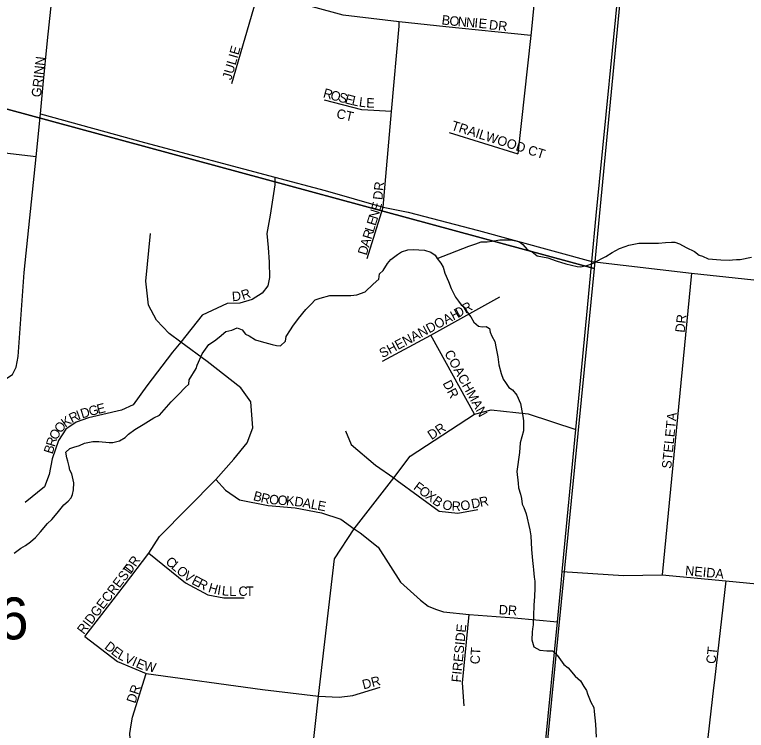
# Model space of a CAD drawing. Extents: x 1310247 to 1552180, y 377264 to 706493.
# Drawn here: x 1437638 to 1441493, y 490370 to 494144 of the extents above; entities that cross this region are included whole.
import ezdxf

# ---------------------------------------------------------------- set-up
doc = ezdxf.new("R2010")
doc.units = 0
for name, color, linetype in [('GM_X_Minor_River', 7, 'Continuous'), ('GM_X_Section', 7, 'Continuous'), ('GM_X_Section_Text', 7, 'Continuous'), ('GM_X_Township_Road', 7, 'Continuous'), ('GM_X_Township_Subdivision', 7, 'Continuous'), ('GM_X_Township_Subdivision_Text', 7, 'Continuous')]:
    doc.layers.add(name, color=color, linetype=linetype)

msp = doc.modelspace()

# ---------------------------------------------------------------- linework, layer by layer
at = {"layer": 'GM_X_Minor_River'}
for points in [[(1439863.8, 492857.5), (1440030.5, 492923), (1440067, 492935.9), (1440095.4, 492945.1), (1440127.5, 492946.1), (1440153.7, 492949.3), (1440194, 492956.1), (1440230.2, 492957), (1440252.2, 492956.3), (1440278.2, 492951.5), (1440298, 492944.9), (1440315.7, 492932.3), (1440339, 492905.5), (1440364.7, 492892.7), (1440390.2, 492871.8), (1440448.1, 492862), (1440491.8, 492844.6), (1440541.5, 492829.1), (1440601.3, 492815.2), (1440619.3, 492814.7), (1440653.6, 492821.6), (1440682, 492830.8), (1440735, 492859.3), (1440753.4, 492868.8), (1440786.1, 492889.8), (1440824.8, 492910.7), (1440855.3, 492921.8), (1440873.5, 492927.3), (1440926, 492937.8), (1440982.2, 492938), (1441030.4, 492938.6), (1441066.6, 492941.5), (1441098.8, 492944.5), (1441116.8, 492944), (1441140.6, 492935.2), (1441176.2, 492916.1), (1441219.7, 492894.7), (1441245.3, 492875.8), (1441263.1, 492869.2), (1441292.8, 492856.3), (1441358.9, 492850.3), (1441403, 492848.9), (1441421.1, 492850.4), (1441441.2, 492851.8), (1441461.3, 492853.2), (1441519.9, 492865.4)], [(1438314.9, 491982), (1438371.5, 492017), (1438401.7, 492032.5), (1438463, 492101.5), (1438501.7, 492140.8), (1438536.4, 492178.3), (1438554.8, 492196), (1438557.2, 492218), (1438594.4, 492277.5), (1438598.7, 492295.5), (1438625.9, 492355.1), (1438660.8, 492404.6), (1438691.2, 492424.1), (1438715.5, 492443.6), (1438750.1, 492473), (1438782.2, 492480.4), (1438810.3, 492491.9), (1438836.1, 492481.3), (1438853.6, 492458.8), (1438873.4, 492450.4), (1438906.9, 492429.6), (1438936.7, 492421), (1438994.2, 492403.7), (1439018.1, 492399.2), (1439038, 492396.8), (1439064.4, 492422.3), (1439068.9, 492446.3), (1439091.6, 492482), (1439104, 492501.8), (1439132.7, 492541.4), (1439171.6, 492588.8), (1439200.1, 492616.3), (1439220.6, 492640), (1439246.7, 492649.5), (1439298.9, 492662.5), (1439352.8, 492663.3), (1439408.7, 492662.2), (1439440.7, 492665.5), (1439485, 492682.7), (1439527.7, 492722), (1439556.2, 492749.5), (1439560.8, 492777.5), (1439579.1, 492795.2), (1439601.8, 492830.9), (1439620.2, 492852.6), (1439654.6, 492878), (1439676.9, 492893.6), (1439709.1, 492902.9), (1439737, 492904.4), (1439767, 492903.7), (1439796.8, 492901.1), (1439830.6, 492890.4), (1439854.2, 492875.8), (1439863.8, 492857.5), (1439883.3, 492833), (1439894.9, 492812.7), (1439904.2, 492780.4), (1439923.2, 492735.8), (1439938.5, 492699.4), (1439961.5, 492654.7), (1439977, 492632.3), (1439990.6, 492613.9), (1440012.2, 492597.4), (1440023.7, 492573.1), (1440041.2, 492550.6), (1440056.6, 492522.2), (1440082.2, 492501.6), (1440102, 492497.1), (1440122, 492498.8), (1440139.8, 492488.3), (1440143.4, 492470.2), (1440152.9, 492447.9), (1440168.3, 492419.5), (1440175.6, 492383.2), (1440184.6, 492338.8), (1440189.8, 492296.5), (1440200.8, 492252.1), (1440212.2, 492221.8), (1440223.8, 492203.4), (1440241.2, 492177), (1440260.9, 492164.5), (1440284.3, 492137.9), (1440303.4, 492093.3), (1440307, 492073.2), (1440316, 492026.8), (1440319.5, 492002.6), (1440318.4, 491948.4), (1440301.2, 491886.5), (1440298.1, 491834.4), (1440284.1, 491734.3), (1440290.9, 491673.9), (1440292.3, 491647.8), (1440303.6, 491615.4), (1440309.2, 491593.2), (1440312.5, 491563), (1440320.2, 491544.8), (1440333.5, 491512.3), (1440351.7, 491427.6), (1440357, 491395.4), (1440361.6, 491323), (1440366.4, 491264.7)], [(1437634.3, 491303.4), (1437670.8, 491330.7), (1437695, 491344.3), (1437721.3, 491363.8), (1437747.8, 491387.4), (1437774.3, 491416.9), (1437811.2, 491460.3), (1437833.5, 491482), (1437862.2, 491515.5), (1437897, 491559), (1437919.4, 491578.6), (1437935.7, 491596.3), (1437942, 491614.3), (1437948.5, 491638.2), (1437949.3, 491674.4), (1437938.3, 491722.8), (1437928.7, 491741.1), (1437925.1, 491761.2), (1437917.7, 491789.5), (1437912.1, 491807.7), (1437906.6, 491835.9), (1437929, 491855.5), (1437949.1, 491863.1), (1437979.2, 491872.5), (1438005.4, 491884.1), (1438031.5, 491889.5), (1438049.5, 491893.2), (1438081.5, 491892.5), (1438135.3, 491887.4), (1438155.2, 491887), (1438189.3, 491896.3), (1438219.6, 491913.7), (1438238, 491931.4), (1438270.4, 491956.9), (1438314.9, 491982)], [(1440366.4, 491264.7), (1440369.7, 491234.5), (1440371.4, 491216.4), (1440374.6, 491178.1), (1440378.1, 491156), (1440379.4, 491119.8), (1440376.5, 491075.7), (1440373.5, 491029.6), (1440372.4, 490973.3), (1440369.5, 490927.2), (1440367, 490905.2), (1440364.7, 490887.2), (1440363.8, 490847), (1440373.1, 490810.7), (1440404.6, 490792), (1440442.5, 490789.1), (1440472.4, 490788.5), (1440495.9, 490766), (1440530.9, 490717), (1440554.5, 490700.5), (1440591.5, 490655.5), (1440619, 490630.9), (1440636.3, 490600.4), (1440651.9, 490580), (1440655.5, 490561.8), (1440674.6, 490519.2), (1440690, 490490.8), (1440691.5, 490468.7), (1440698.1, 490402.3), (1440702.7, 490333.9)]]:
    msp.add_lwpolyline(points, dxfattribs=at)
at = {"layer": 'GM_X_Section'}
for points in [[(1435471.2, 499726.6), (1441204.6, 498140.6), (1440691.2, 492805.3), (1434995.6, 494353)], [(1434995.6, 494353), (1440691.2, 492805.3), (1440171.6, 487550.2), (1434523.9, 489065.4)]]:
    msp.add_lwpolyline(points, close=True, dxfattribs=at)
at = {"layer": 'GM_X_Township_Road'}
for points in [[(1440075.3, 486189.5), (1440078.4, 486259.7), (1440079.3, 486648.8), (1440110.2, 487008.8), (1440147.5, 487410.5), (1440199, 487926), (1440286.6, 488803.3), (1440287.7, 488814.4), (1440345.3, 489393.7), (1440433.9, 490284.4), (1440498.5, 490942), (1440517.4, 491143.5), (1440522, 491207.4), (1440594.8, 491956.1), (1440657.1, 492597.6), (1440679.8, 492841.4), (1440702.4, 493084.3), (1440840.8, 494488.3), (1440884.8, 494943.8), (1440887.9, 494974.8), (1440891, 495006.8)], [(1433702.7, 491387.2), (1433896.9, 491482.8), (1434035.3, 491546.2), (1434171.6, 491591.7), (1434375.3, 491641.9), (1434710.6, 491714.9), (1434801.6, 491758.4), (1435236.4, 491956.4), (1435669.3, 492140.2), (1435775.4, 492168.6), (1435925, 492199.9), (1436237.6, 492256.7), (1436571.1, 492316.4), (1436669.6, 492315.4), (1437183.1, 492261.1), (1437537.7, 492224.9), (1437592, 492222.7), (1437626.3, 492246.3), (1437645.5, 492284.9), (1437655.6, 492340.6), (1437687.7, 492784.8), (1437751.6, 493393.4), (1437774.4, 493620)], [(1437774.4, 493620), (1438322.3, 493469.7), (1439008.5, 493285.9), (1439273.8, 493215.4), (1439579.9, 493129.2), (1439710.8, 493101.7), (1440082, 493005), (1440679.8, 492841.4), (1441204.7, 492780.6), (1441714.2, 492726.8), (1442667.4, 492637.5), (1442992.2, 492599.4), (1443157.4, 492587.5), (1443532.5, 492544.6), (1443863.8, 492520.3), (1444719.2, 492429.1), (1445497, 492347.4)]]:
    msp.add_lwpolyline(points, dxfattribs=at)
at = {"layer": 'GM_X_Township_Subdivision'}
for points in [[(1438781.4, 493779.7), (1438921.8, 494263), (1438949, 494374.8), (1439035.7, 494726.8), (1439094.4, 494924.7), (1439193, 495094.9), (1439277.9, 495285.6), (1439398.8, 495716.4), (1439522.6, 496100.9), (1439593.2, 496358.2), (1439603.6, 496409), (1439659.3, 496679.9), (1439707.8, 497022.1), (1439728.8, 497224.4)], [(1439762, 495211.9), (1440349.5, 495063.9), (1440391.1, 495013.9), (1440420.7, 494951), (1440435.6, 494851.3), (1440404.6, 494525.3), (1440362.7, 494084), (1440357.1, 494032.6), (1440289, 493409.7)], [(1437774.4, 493620), (1437787.7, 493776), (1437810.5, 494007.4), (1437836.2, 494256.7), (1437843.5, 494332.2), (1437871.6, 494523.6), (1437876.3, 494673.5), (1437866.2, 494738.4), (1437832.9, 494832.7)], [(1440357.1, 494032.6), (1439909.1, 494079.9), (1439664.7, 494106.1), (1439369, 494140.1), (1438921.8, 494263), (1438676.4, 494324.3), (1438482.1, 494378.3), (1438270.5, 494434.6), (1438001, 494504.2), (1437871.6, 494523.6)], [(1437751.6, 493393.4), (1437418.7, 493432.4), (1437281, 493456.6), (1437022.7, 493534.6), (1436588.7, 493701.1), (1435832.2, 493899.7), (1434987.3, 494125.8), (1434548.4, 494172.7), (1434295.1, 494192.4), (1433855.4, 494224.5)], [(1439495.6, 492858.4), (1439579.9, 493129.2), (1439623.8, 493632.6), (1439663, 494082.2), (1439664.7, 494106.1)], [(1439623.8, 493632.6), (1439466.3, 493641.4), (1439270.5, 493692)], [(1439927.7, 493522.9), (1440289, 493409.7)], [(1439008.5, 493285.9), (1439008.8, 493246.4), (1438983.3, 493085.9), (1438966.9, 492989.9), (1438973.4, 492916.6), (1438978.7, 492837.8), (1438980.8, 492757.3), (1438971.2, 492712.8), (1438942.1, 492674.2), (1438888.7, 492642.4), (1438824.1, 492622.8), (1438756.9, 492620.2), (1438626.1, 492558.8), (1438513.9, 492416.4), (1438468.9, 492364), (1438334.8, 492186.4), (1438261.3, 492086.1), (1438200.3, 492058.2), (1438027, 492017.4), (1437962.2, 491995.3), (1437907.5, 491958.3), (1437869.5, 491898.8), (1437835.9, 491801.8), (1437819.6, 491719.7), (1437794.1, 491653.9), (1437693.3, 491571.2)], [(1438006.8, 490864.5), (1438216.3, 491135.9), (1438344.7, 491304.2), (1438400.2, 491392.7), (1438698.6, 491693.3), (1438793.2, 491800), (1438863.4, 491885.9), (1438893, 491965.7), (1438882.5, 492102.8), (1438828.7, 492175.7), (1438651.8, 492314.5), (1438513.9, 492416.4), (1438451.6, 492461.9), (1438385.2, 492532.7), (1438343.4, 492611.7), (1438329.4, 492739), (1438354.2, 492989.6)], [(1441204.7, 492780.6), (1441050.1, 491190)], [(1439576.5, 492317.1), (1439831.5, 492454.2), (1440194.1, 492655.5)], [(1440060.5, 492036.9), (1439831.5, 492454.2)], [(1440286.6, 488803.3), (1440093.6, 488812.6), (1439960.5, 488827.9), (1439827.5, 488841.7), (1439643.9, 488855.5), (1439484.9, 488892.2), (1439363, 488980.1), (1439234.7, 489144.9), (1439115, 489320.1), (1439182.7, 490038.9), (1439237.9, 490550.5), (1439323.2, 491275.2), (1439427.5, 491433.2), (1439635, 491700.5), (1439722.2, 491814.8), (1440060.5, 492036.9), (1440149, 492059.5), (1440343.2, 492038.6), (1440594.8, 491956.1)], [(1439381.1, 491949.5), (1439411.7, 491877.3), (1439538.3, 491767.9), (1439635, 491700.5), (1439652.8, 491688.1), (1439874.9, 491525), (1439973.7, 491514.6), (1440077.8, 491533.7)], [(1438698.6, 491693.3), (1438748.1, 491636.9), (1438822.6, 491584.9), (1438973.6, 491555.4), (1439115.9, 491543.2), (1439254.6, 491517.2), (1439357, 491484.3), (1439427.5, 491433.2), (1439457.6, 491411.4), (1439553, 491335), (1439670.8, 491151.1), (1439776, 491057), (1439816.7, 491024.9), (1439854.9, 491009.3), (1439898.3, 490994.5), (1440031.9, 490980.6), (1440270.4, 490964.1), (1440498.5, 490942)], [(1438344.7, 491304.2), (1438538.6, 491148.2), (1438655.5, 491085), (1438739.4, 491068.9), (1438847.8, 491068.2)], [(1440522, 491207.4), (1440846.4, 491186.6), (1441050.1, 491190), (1441384.9, 491157.6), (1441729.4, 491124.1), (1441849.1, 491112)], [(1441384.9, 491157.6), (1441325.4, 490635)], [(1440006.2, 490500.1), (1439998, 490621), (1440031.9, 490980.6)], [(1438006.8, 490864.5), (1438179.9, 490733.4), (1438331.2, 490669.5), (1438943.2, 490585), (1439237.9, 490550.5), (1439347.4, 490545.1), (1439420.3, 490553.8), (1439564.3, 490597.1)], [(1438251.7, 490399.9), (1438258.3, 490439.5), (1438331.2, 490669.5)], [(1441325.4, 490635), (1441320.8, 490595), (1441276.9, 490209.6), (1441230.8, 489758.2), (1441184.8, 489309), (1441170.8, 489171.9), (1441148.5, 488961)], [(1438371.4, 489860.2), (1438374.5, 489924.6), (1438343.5, 490058), (1438270.9, 490222.5), (1438248.3, 490300.2), (1438244, 490353.8), (1438251.7, 490399.9)]]:
    msp.add_lwpolyline(points, dxfattribs=at)

# ---------------------------------------------------------------- texts
at = {"layer": 'GM_X_Section_Text'}
msp.add_text('16', height=221, rotation=0, dxfattribs=at).set_placement((1437382.1, 490849.6))
at = {"layer": 'GM_X_Township_Subdivision_Text'}
for s, rotation, p in [('B', 352.5225, (1439885.5, 494092.5)), ('O', 354.8461, (1439927, 494087.1)), ('N', 355.139, (1439971.1, 494083.1)), ('N', 355.1311, (1440014.9, 494079.4)), ('I', 355.1285, (1440058.7, 494075.7)), ('E', 355.1309, (1440080.7, 494073.8)), ('DR', 353.9883, (1440135.3, 494066.3)), ('JULIE', 74.0542, (1438778.9, 493795.5)), ('GRINN', 83.5178, (1437775.4, 493706)), ('R', 345.1429, (1439259.7, 493707.7)), ('O', 345.1429, (1439297.9, 493697.5)), ('S', 345.1429, (1439340.5, 493686.2)), ('E', 345.1429, (1439374.5, 493677.2)), ('L', 347.6191, (1439410.8, 493667.6)), ('L', 352.5714, (1439449.8, 493659.3)), ('E', 357.5238, (1439489.4, 493654.3)), ('CT', 347.4661, (1439330.1, 493599.3)), ('TRAILWOOD CT', 342.2553, (1439934.8, 493537.9)), ('DR', 83.9946, (1439575.1, 493164.7)), ('E', 73.6659, (1439562.5, 493103.7)), ('N', 73.0652, (1439549.5, 493061)), ('E', 73.0674, (1439539.3, 493027.4)), ('L', 73.06, (1439529, 492993.7)), ('R', 73.0705, (1439517.5, 492955.8)), ('A', 73.0645, (1439504.7, 492913.7)), ('D', 73.0684, (1439491.9, 492871.6)), ('D', 5.2419, (1438784.7, 492632)), ('R', 18.5774, (1438840.7, 492638.6)), ('DR', 29.3587, (1439971.3, 492542.7)), ('SHENANDOAH', 27.897, (1439575.5, 492331.7)), ('DR', 83.9889, (1441167.8, 492465.1)), ('COACHMAN', 298.7798, (1439900.5, 492358.6)), ('DR', 297.9017, (1439891.4, 492199.9)), ('D', 16.9211, (1437993, 492013.9)), ('G', 14.5266, (1438034.6, 492026.6)), ('E', 14.0329, (1438077, 492037.6)), ('K', 35.5059, (1437904.9, 491965)), ('R', 26.4401, (1437938.9, 491989.5)), ('I', 20.3155, (1437973.1, 492006.6)), ('STELETA', 84.289, (1441097.3, 491747.8)), ('O', 50.3945, (1437879.4, 491933.4)), ('DR', 33.6884, (1439834.3, 491899.9)), ('O', 60.6238, (1437859.1, 491897)), ('R', 73.0435, (1437848.7, 491861.8)), ('B', 73.0321, (1437837.1, 491823.9)), ('F', 323.0727, (1439735.2, 491644.4)), ('O', 323.079, (1439763.4, 491623.2)), ('B', 345.469, (1438891.5, 491584.4)), ('R', 346.7632, (1438931.1, 491574.2)), ('O', 354.7106, (1438977.1, 491563.9)), ('O', 356.4348, (1439022.5, 491559.7)), ('K', 355.9642, (1439066.3, 491557)), ('D', 351.4557, (1439109.2, 491554)), ('X', 323.079, (1439798.5, 491596.8)), ('B', 324.4777, (1439834.8, 491569.6)), ('R', 11.8247, (1440091.9, 491547.6)), ('A', 349.3501, (1439152.2, 491547.5)), ('L', 349.2822, (1439195.5, 491539.4)), ('E', 349.2848, (1439230.1, 491532.9)), ('O', 349.0842, (1439888.4, 491537.4)), ('R', 357.433, (1439939.5, 491528.1)), ('O', 11.0127, (1439991.9, 491527.3)), ('D', 11.82, (1440048.8, 491538.6)), ('DR', 55.4903, (1438247.8, 491189.1)), ('C', 319.8742, (1438428.8, 491252.5)), ('L', 319.8933, (1438459.1, 491227)), ('RIDGECREST', 52.4714, (1438001.7, 490872.7)), ('O', 319.8824, (1438486, 491204.3)), ('V', 325.2101, (1438523.7, 491172.8)), ('NEIDA', 354.686, (1441169.1, 491188.5)), ('E', 332.8524, (1438566.1, 491144)), ('R', 332.8568, (1438597.4, 491127.9)), ('H', 344.0243, (1438654.4, 491100.2)), ('I', 350.3865, (1438702.6, 491086.8)), ('L', 354.1165, (1438727.8, 491082.6)), ('L', 0.0523, (1438768.5, 491078.7)), ('C', 0, (1438816.9, 491078.7)), ('T', 0, (1438856.5, 491078.7)), ('DR', 356.9833, (1440187.6, 490981.9)), ('FIRESIDE', 84.472, (1439988.5, 490621.4)), ('D', 322.3455, (1438107.3, 490803.9)), ('E', 322.3323, (1438142.1, 490777)), ('L', 330.4592, (1438176.3, 490751.3)), ('CT', 86.8222, (1440087.6, 490717.5)), ('CT', 83.6631, (1441330.5, 490718.4)), ('V', 336.2841, (1438211.8, 490731.5)), ('I', 336.4634, (1438252.3, 490713.7)), ('E', 336.4481, (1438272.4, 490705)), ('W', 348.1928, (1438315.2, 490687.6)), ('DR', 14.7419, (1439476.3, 490585.6)), ('DR', 71.5687, (1438273, 490509.1))]:
    msp.add_text(s, height=50, rotation=rotation, dxfattribs=at).set_placement(p)

doc.saveas('drawing.dxf')
